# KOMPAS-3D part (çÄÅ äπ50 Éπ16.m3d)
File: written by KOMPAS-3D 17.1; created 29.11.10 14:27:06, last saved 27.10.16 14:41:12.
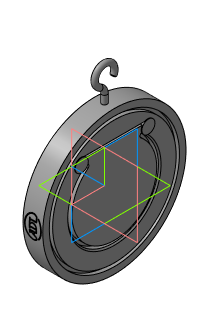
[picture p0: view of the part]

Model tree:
1. Плоскость XY
2. Плоскость ZX
3. Плоскость ZY
4. Ось X
5. Ось Y
6. Ось Z
7. Начало координат
8. Операция без истории:2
